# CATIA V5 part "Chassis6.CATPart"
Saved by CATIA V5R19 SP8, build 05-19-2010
Part number: Chassis6
Bounding box of the stored display mesh (mm): x -165 to -110, y -89.553 to 90.043, z -84.36 to 163.148
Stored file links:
  G:\EU_thinkMotion\CFAO_2010\MMS_groupe2\MMS_groupe2\A reprendre\jcauchy\Chassis6.CATPart
  G:\EU_thinkMotion\CFAO_2010\MMS_groupe2\MMS_groupe2\A reprendre\jcauchy\Squelette_biellette8.CATPart
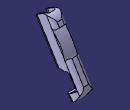
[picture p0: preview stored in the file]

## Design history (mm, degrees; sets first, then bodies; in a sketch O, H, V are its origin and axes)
Parameters
  Longueurchassis_chassis = 320 mm
  Largeurchassis_chassis6 = 50 mm
  Hauteurchassis_chassis6 = 60 mm
  Largeurpoche_chassis6 = 30 mm
  Hauteurpoche_chassis6 = 40 mm
  Positionnementpoche_chassis6 = 20 mm
  Profondeurpoche_chassis6 = 242 mm
  Rayonroue_chassis6 = 30 mm
  Rayonfixation_chassis6 = 2.5 mm
  Longueurbiellette_biellette8 = 50 mm
Set1
  Plane1: stored without definition
  Sketch1 on Plane1, origin (0, 50.9141, 31.4147), H (-1, 0, 0), V (0, -0.5251, 0.851)
    line L1 (115, 170.261) -> (165, 170.261)
    line L2 (165, 170.261) -> (165, -149.739)
    line L3 (165, -149.739) -> (115, -149.739)
    line L4 (115, -149.739) -> (115, 170.261)
    reference projected line E1 (120, 155.261) -> (140, 155.261) from Line1
    reference projected line E2 (140, 27.261) -> (140, 155.261) from Line2
    length L1 = 50 {= Largeurchassis_chassis6}
    distance L1 E1 = 15
    length L2 = 320 {= Longueurchassis_chassis}
    distance L2 E2 = 25 {= Largeurchassis_chassis6/2}
    horizontal: L1 H, L3 H
    vertical: L2 V, L4 V
  Line1 to Line6: stored without definition
  DatumPoint1
  DatumPoint2
  Plane2: stored without definition
  DatumPoint3
  Plane3: stored without definition
  DatumPoint4
  DatumPoint5
  Plane4: stored without definition
  Line7: stored without definition
  Line8: stored without definition
  Plane5 to Plane11: stored without definition
  DatumPoint6
  DatumPoint7
  Line9: stored without definition
  Point1 to Point3: stored without definition
  Plane12: stored without definition
  Plane13: stored without definition
Body1 (main body)
  Pad1: profile Sketch1, direction (0, -0.851, -0.5251), length 60 {= Hauteurchassis_chassis6}
  Sketch2 on face of Pad1 from Sketch1.L1, origin (0, -89.4044, 144.8988), H (1, 0, 0), V (0, 0.851, 0.5251)
    line L1 (-155, 39.8258) -> (-125, 39.8258)
    line L2 (-125, 39.8258) -> (-125, -0.1742)
    line L3 (-125, -0.1742) -> (-155, -0.1742)
    line L4 (-155, -0.1742) -> (-155, 39.8258)
    reference projected line E1 (-115, 59.8258) -> (-115, -10.1742) from edge [face of Pad1 from Sketch1.L1 | face of Pad1 from Sketch1.L4]
    reference projected line E2 (-190, 59.8258) -> (-90, 59.8258) from edge [face of Pad1 from Sketch1.L1 | start face of Pad1]
    reference projected line E3 (-190, -0.1742) -> (-90, -0.1742) from edge [end face of Pad1 | face of Pad1 from Sketch1.L1]
    length L1 = 30 {= Largeurpoche_chassis6}
    distance L2 E1 = 10 {= Largeurchassis_chassis6 /2-Largeurpoche_chassis6 /2}
    distance L1 E2 = 20 {= Positionnementpoche_chassis6}
    distance L3 E3 = 0
    horizontal: L1 H, L3 H
    vertical: L2 V, L4 V
  Pocket1: profile Sketch2, direction (0, 0.5251, -0.851), length 242 {= Profondeurpoche_chassis6}
  Body2
    Sketch3 on face of Pad1 from Sketch1.L1, origin (0, -89.4044, 144.8988), H (1, 0, 0), V (0, 0.851, 0.5251)
      point P1 (-115, -0.1742)
      line L1 (-115, -0.1742) -> (-115, 4.8258)
      point P2 (-115, 4.8258)
      spline S1 through (-115, 4.8258) (-117.5, 19.8258) (-115, 44.8258)
      point P3 (-140, 39.8258)
      spline S2 through (-115, 44.8258) (-120, 54.8258) (-130, 59.8258)
      line L2 (-115, -0.1742) -> (-81.6311, -0.1742)
      line L3 (-81.6311, -0.1742) -> (-81.6311, 87.5232)
      line L4 (-81.6311, 87.5232) -> (-140, 87.5232)
      point P7 (-130, 59.8258)
      reference projected line E1 (-165, 59.8258) -> (-115, 59.8258) from edge [face of Pad1 from Sketch1.L1 | start face of Pad1]
      reference projected line E2 (-115, 59.8258) -> (-115, -0.1742) from edge [face of Pad1 from Sketch1.L1 | face of Pad1 from Sketch1.L4]
      reference projected point E3 (-115, -0.1742) from vertex [face of Pad1 from Sketch1.L1 | end face of Pad1 | face of Pad1 from Sketch1.L4]
      reference projected line E4 (-165, 59.8258) -> (-115, 59.8258) from edge [face of Pad1 from Sketch1.L1 | start face of Pad1]
      reference projected line E5 (-165, 59.8258) -> (-115, 59.8258) from edge [face of Pad1 from Sketch1.L1 | start face of Pad1]
      reference projected line E6 (-115, 59.8258) -> (-115, -0.1742) from edge [face of Pad1 from Sketch1.L1 | face of Pad1 from Sketch1.L4]
      reference projected line E7 (-165, -0.1742) -> (-115, -0.1742) from edge [end face of Pad1 | face of Pad1 from Sketch1.L1]
      line L5 (-130, 59.8258) -> (-140, 59.8258)
      line L6 (-140, 87.5232) -> (-140, 59.8258)
      reference projected line E8 (-115, 59.8258) -> (-115, -0.1742) from edge [face of Pad1 from Sketch1.L1 | face of Pad1 from Sketch1.L4]
      reference projected line E9 (-140, 4.8258) -> (-140, 59.8258) from Line5
      point P9 (-115, 4.8258)
      point P10 (-115, 44.8258)
      point P11 (-115, 44.8258)
      point P12 (-130, 59.8258)
      point P13 (-120, 54.8258)
      point P14 (-117.5, 19.8258)
      distance P7 E1 = 0
      distance P11 E2 = 0
      length L3 = 87.6974
      length L4 = 58.3689
      distance P13 E4 = 5
      distance P11 E5 = 15
      distance P14 E6 = 2.5
      distance P14 E7 = 20
      length L1 = 5
      distance P13 E8 = 5
      length L5 = 10
      distance L6 E9 = 0
      coincidence: P9 P2, P10 L1, P11 P10, P12 P7, P1 E3
      horizontal: L2 H, L4 H, L5 H
      vertical: L3 V, L6 V
    Pad2: profile Sketch3, direction (0, 0.5251, -0.851), length 320 {= Longueurchassis_chassis}
    Mirror1: of Pad2, Sketch3, about face of Pad2 from Sketch3.L6
  Remove1: tool Body2
  Body3
    Sketch4 on face of Pad1 from Sketch1.L1, origin (0, -89.4044, 144.8988), H (1, 0, 0), V (0, 0.851, 0.5251)
      spline S1 through (-155, 7.5) (-158, 22.3258) (-155, 39.8258) (-140, 41.8258)
      line L1 (-140, 41.8258) -> (-140, 0)
      point P1 (-140, 41.8258)
      point P2 (-140, 0)
      line L2 (-140, 0) -> (-155, 0)
      line L3 (-155, 0) -> (-155, 7.5)
      point P4 (-155, 7.5)
      reference projected line E1 (-140, 4.8258) -> (-140, 59.8258) from Line6
      reference projected point E2 (-155, 39.8258) from vertex [face of Pocket1 from Sketch2.L4 | face of Pocket1 from Sketch2.L1 | face of Pad1 from Sketch1.L1]
      reference projected line E3 (-155, 39.8258) -> (-155, -0.1742) from edge [face of Pad1 from Sketch1.L1 | face of Pocket1 from Sketch2.L4]
      reference projected line E4 (-125, 39.8258) -> (-155, 39.8258) from edge [face of Pad1 from Sketch1.L1 | face of Pocket1 from Sketch2.L1]
      reference projected line E5 (-155, 39.8258) -> (-155, -0.1742) from edge [face of Pad1 from Sketch1.L1 | face of Pocket1 from Sketch2.L4]
      reference projected line E6 (-125, 39.8258) -> (-155, 39.8258) from edge [face of Pad1 from Sketch1.L1 | face of Pocket1 from Sketch2.L1]
      point P5 (-140, 41.8258)
      point P6 (-155, 7.5)
      point P7 (-155, 39.8258)
      point P8 (-158, 22.3258)
      distance L1 E1 = 0
      distance L3 E3 = 0
      distance P1 E4 = 2
      length L3 = 7.5 {= Hauteurchassis_chassis6 -Positionnementpoche_chassis6 -Rayonroue_chassis6 +Rayonfixation_chassis6 -5mm}
      distance P8 E5 = 3
      distance P8 E6 = 17.5 {= (Hauteurpoche_chassis6-5mm)/2}
      coincidence: P5 P1, P2 H, P7 E2, P4 P6
      vertical: L1 V, L3 V
      horizontal: L2 H
    Pad3: profile Sketch4, direction (0, 0.5251, -0.851), length 242 {= Profondeurpoche_chassis6}
    Mirror2: of Pad3, Sketch4, about face of Pad3 from Sketch4.L1
  Remove2: tool Body3
  Sketch5 on face of Pocket1 from Sketch2.L2, origin (-125, 0, 0), H (0, -1, 0), V (0, 0, 1)
    circle A1 centre (77.4209, 134.6673) radius 2.5
    point P1 (77.4209, 134.6673)
    reference projected point E1 (77.4209, 134.6673) from vertex of DatumPoint2
    radius A1 = 2.5 {= Rayonfixation_chassis6}
    distance P1 E1 = 0
  Pad4: profile Sketch5, direction (-1, 0, 0), up to the existing solid (limit type 2)
  Sketch6 on Plane2, origin (-120, 0, 0), H (0, -1, 0), V (0, 0, 1)
    circle A1 centre (43.8144, 80.2007) radius 2.5
    point P1 (43.8144, 80.2007)
    reference projected point E1 (43.8144, 80.2007) from vertex of DatumPoint3
    radius A1 = 2.5 {= Rayonfixation_chassis6}
    distance E1 P1 = 0
  Pad5: profile Sketch6, direction (-1, 0, 0), up to face of Pocket1 from Sketch2.L4
  Sketch7 on Plane3, origin (-120, 0, 0), H (0, -1, 0), V (0, 0, 1)
    circle A1 centre (10.2078, 25.7342) radius 2.5
    point P1 (10.2078, 25.7342)
    point P2 (42.9656, 0)
    reference projected point E1 (10.2078, 25.7342) from vertex of DatumPoint5
    radius A1 = 2.5 {= Rayonfixation_chassis6}
    distance P1 E1 = 0
  Pad6: profile Sketch7, direction (-1, 0, 0), up to face of Pocket1 from Sketch2.L4
  Body4
    Sketch8 on Plane4, origin (-120, 0, 0), H (0, -1, 0), V (0, 0, 1)
      spline S1 through (-26.8576, 38.0287) (-7.2768, 83.0224) (28.2781, 127.3879)
      reference projected line E1 (60.6176, 107.434) -> (13.8105, 136.3146) from Line7
      reference projected line E2 (-22.8196, 17.9117) -> (-49.2018, 34.1899) from Line8
      spline S2 through (28.2781, 127.3879) (15.1567, 127.1635) (8.2683, 134.8048)
      spline S3 through (-26.8576, 38.0287) (-33.4691, 48.6782) (-41.2747, 51.1023)
      line L1 (-41.2747, 51.1023) -> (8.2683, 134.8048)
      point P1 (-41.2747, 51.1023)
      point P2 (8.2683, 134.8048)
      reference projected line E3 (-129.5424, -96.0191) -> (38.4902, 176.3135) from edge [face of Mirror1 | face of Mirror1]
      reference projected line E4 (-129.5424, -96.0191) -> (38.4902, 176.3135) from edge [face of Mirror1 | face of Mirror1]
      reference projected line E5 (-129.5424, -96.0191) -> (38.4902, 176.3135) from edge [face of Mirror1 | face of Mirror1]
      point P3 (28.2781, 127.3879)
      point P4 (-26.8576, 38.0287)
      point P6 (28.2781, 127.3879)
      point P7 (-26.8576, 38.0287)
      point P8 (-41.2747, 51.1023)
      point P9 (8.2683, 134.8048)
      distance P3 E1 = 0
      distance P4 E2 = 15
      distance E3 P6 = 17
      distance P7 E4 = 17
      distance S1 E5 = 10
      coincidence: P6 P3, P7 P4, P8 P1, P9 P2
    Pad7: profile Sketch8, direction (-1, 0, 0), length 50 {= Largeurchassis_chassis6}, mirrored extent
  Remove3: tool Body4
  Fillet1: radius 35, on edge [face of Pad1 from Sketch1.L1 | face of Mirror1] (x2); edge [face of Pad2 from Sketch3.S2 | face of Pad1 from Sketch1.L1]
  Body5
    Sketch9 on Plane8, origin (-120, 0, 0), H (0, 1, 0), V (0, 0, 1)
      spline S1 through (-1.1882, 1.594) (6.4015, 5.0473) (19.8019, 2.3679) (29.2662, 5.4287) (37.4205, 6.3938) (43.6068, 2.459) (48.2583, -3.2963)
      line L1 (48.2583, -3.2963) -> (70.0651, -37.7114)
      point P1 (48.2583, -3.2963)
      point P2 (70.0651, -37.7114)
      spline S2 through (70.0651, -37.7114) (71.3067, -41.9165) (69.3395, -45.6606)
      line L2 (69.3395, -45.6606) -> (45.1151, -61.9319)
      point P3 (69.3395, -45.6606)
      point P4 (45.1151, -61.9319)
      spline S3 through (45.1151, -61.9319) (41.8219, -62.2467) (37.2332, -60.6759)
      line L3 (37.2332, -60.6759) -> (-1.1882, 1.594)
      point P5 (37.2332, -60.6759)
      point P6 (-1.1882, 1.594)
      reference projected line E1 (-89.5526, 144.8073) -> (78.48, -127.5252) from edge [end face of Pad1 | face of Pad2]
      point P7 (48.2583, -3.2963)
      point P8 (-1.1882, 1.594)
      point P9 (70.0651, -37.7114)
      point P10 (69.3395, -45.6606)
      point P11 (45.1151, -61.9319)
      point P12 (37.2332, -60.6759)
      angle L3 E1 = 0
      distance P9 L3 = 40 {= Hauteurchassis_chassis6 -20mm}
      coincidence: P7 P1, P9 P2, P10 P3, P11 P4, P12 P5, P8 P6
    Pad8: profile Sketch9, direction (1, 0, 0), length 60, opposite side length 50
  Remove4: tool Body5
  Body6
    Sketch10 on Plane10, origin (-120, 0, 0), H (0, 1, 0), V (0, 0, 1)
      spline S1 through (86.4823, -26.2312) (89.9199, -40.8388) (75.7792, -64.4239) (55.0964, -84.1673) (49.3747, -80.354)
      line L1 (49.3747, -80.354) -> (26.6709, -94.3625)
      point P1 (49.3747, -80.354)
      line L2 (26.6709, -94.3625) -> (59.6001, -139.1744)
      point P3 (59.6001, -139.1744)
      line L3 (59.6001, -139.1744) -> (148.7828, -84.1475)
      point P4 (59.6001, -139.1744)
      line L4 (148.7828, -84.1475) -> (102.4117, -16.4025)
      point P6 (102.4117, -16.4025)
      line L5 (102.4117, -16.4025) -> (86.4823, -26.2312)
      point P7 (86.4823, -26.2312)
      point P8 (102.4117, -16.4025)
      reference projected line E1 (-38.4902, 176.3135) -> (129.5424, -96.0191) from edge [face of Pad2 from Sketch3.S2 | face of Mirror1]
      reference projected line E2 (-89.5526, 144.8073) -> (78.48, -127.5252) from edge [end face of Pad1 | face of Pad2]
      reference projected line E3 (82.7352, -124.8997) -> (116.7768, -103.8957) from edge [face of Pad1 from Sketch1.L3 | face of Pad2 from Sketch3.S1]
      point P9 (49.3747, -80.354)
      point P10 (86.4823, -26.2312)
      distance P7 E1 = 0
      distance E2 P1 = 0
      distance L3 E3 = 0
      coincidence: P9 P1, P4 L2, P10 P7, P6 P8, P3 P4
      parallelism: L1 L3, L5 L3
    Pad9: profile Sketch10, direction (1, 0, 0), length 60, mirrored extent
  Remove5: tool Body6
  Sketch11 on Plane11, origin (-120, 0, 0), H (0, 1, 0), V (0, 0, 1)
    circle A1 centre (72.6875, -38.1078) radius 2.5
    point P1 (72.6875, -38.1078)
    reference projected point E1 (72.6875, -38.1078) from Point3
    radius A1 = 2.5 {= Rayonfixation_chassis6}
    distance P1 E1 = 0
  Pad10: profile Sketch11, direction (1, 0, 0), length 10
Body7
  Sketch12 on Plane13, origin (-120, 0, 0), H (0, 1, 0), V (0, 0, 1)
    circle A1 centre (22.8196, 17.9117) radius 2.5
    point P1 (22.8196, 17.9117)
    reference projected point E1 (22.8196, 17.9117) from DatumPoint4
    radius A1 = 2.5
    distance P1 E1 = 0
  Pad11: profile Sketch12, direction (-1, 0, 0), length 9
